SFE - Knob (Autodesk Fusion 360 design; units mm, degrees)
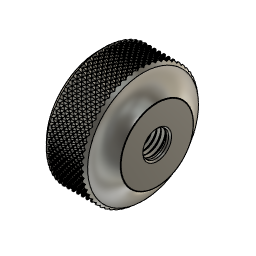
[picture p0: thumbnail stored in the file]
base_feature "Base Feature"
sketch "Sketch2" plane through (0, 0, 31.5) normal (0, -1, 0) x axis (1, 0, 0)
  line L1 (-65.9414, -0.9414) -> (-65.9414, -26.0586)
  line L2 (-63.5, 1.5) -> (-63.5, -28.5)
  line L3 (60.5, -28.5) -> (-60.5, -28.5)
  line L4 (60.5, 1.5) -> (60.5, -28.5)
  line L5 (-60.5, 1.5) -> (60.5, 1.5)
  line L6 (-60.5, -28.5) -> (-60.5, 1.5)
  line L7 (-63.5, 1.5) -> (-60.5, 1.5)
  line L8 (-60.5, -28.5) -> (60.5, -28.5)
  line L9 (-60.5, -28.5) -> (-60.5, -31.5)
  line L10 (60.5, -31.5) -> (-60.5, -31.5)
  line L11 (60.5, -31.5) -> (60.5, -28.5)
  line L12 (-53.9977, -13.5) -> (-85.9977, -13.5)
  line L13 (-70.9414, -1) -> (-70.9414, -13.5)
  line L14 (-75.9414, 6.5) -> (-75.9414, -13.5)
  line L15 (-90.9414, 6.5) -> (-75.9414, 6.5)
  line L16 (-90.9414, -13.5) -> (-90.9414, 6.5)
  line L17 (-90.9414, -13.5) -> (-75.9414, -13.5)
  line L18 (-70.9414, -13.5) -> (-75.9414, -13.5)
  arc A1 centre (-60.5, -28.5) radius 3 clockwise from (-60.5, -31.5) to (-63.5, -28.5)
  arc A2 centre (-66.0139, 7.7017) radius 10 clockwise from (-70.9414, -1) to (-75.9414, 6.5)
  arc A3 centre (-66.0139, 7.7017) radius 10 clockwise from (-58.1692, 1.5) to (-60.5, -0.6408)
  point P19 (-70.9414, -13.5)
  point P21 (-75.9414, -13.5)
  point P24 (-90.9414, -13.5)
  point P26 (-58.1692, 1.5)
  point P28 (-60.5, -0.6408)
  point P20 (-70.9414, -1)
  point P22 (-75.9414, 6.5)
  point P23 (-90.9414, 6.5)
  perpendicular L2 L12
  symmetric L3 L5 L12
  coincident L12 P19
  perpendicular L12 L13
  coincident L12 P21
  perpendicular L12 L14
  perpendicular L14 L15
  coincident L12 P24
  perpendicular L12 L16
  coincident L5 P26
  concentric A2 A3
  coincident L6 P28
  dimension "d233" distance P19 P20 = 12.5
  dimension "d234" distance P21 P22 = 20
  dimension "d235" distance P22 P23 = 15
  dimension "d236" distance L1 L13 = 5
  dimension "d237" diameter A2 = 20
  dimension "d238" distance L13 L14 = 5
revolve "Revolve2" sketch "Sketch2" AlongAngle 360
sketch "Sketch3" plane through (-70.9414, 0, 0) normal (1, 0, 0) x axis (0, 1, 0)
  circle C1 centre (0, 18) radius 12.5
  circle C2 centre (0, 18) radius 5
  concentric C1 C2
  dimension "d240" diameter C2 = 10
extrude "Extrude1" cut sketch "Sketch3" profile of C2 against normal blind 17
chamfer "Chamfer1" distance 2 distance 1 distance 0.5
fillet "Fillet1" radius 0.2 0.2
thread "Thread1"
offset_faces "OffsetFaces5" distance -0.175
offset_faces "OffsetFaces6" distance -0.175
work_axis "WorkAxis2"
work_plane "WorkPlane3" AlongDistance -2
coil_primitive "CoilPrimitive3" Diameter 40 SectionSize 1 TaperAngle 0 Revolutions 0.125 Height -12
mirror "Mirror1" mirrorStitchTolerance 0.1
circular_pattern "C-Pattern1" countU 60 TotalAngle 360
